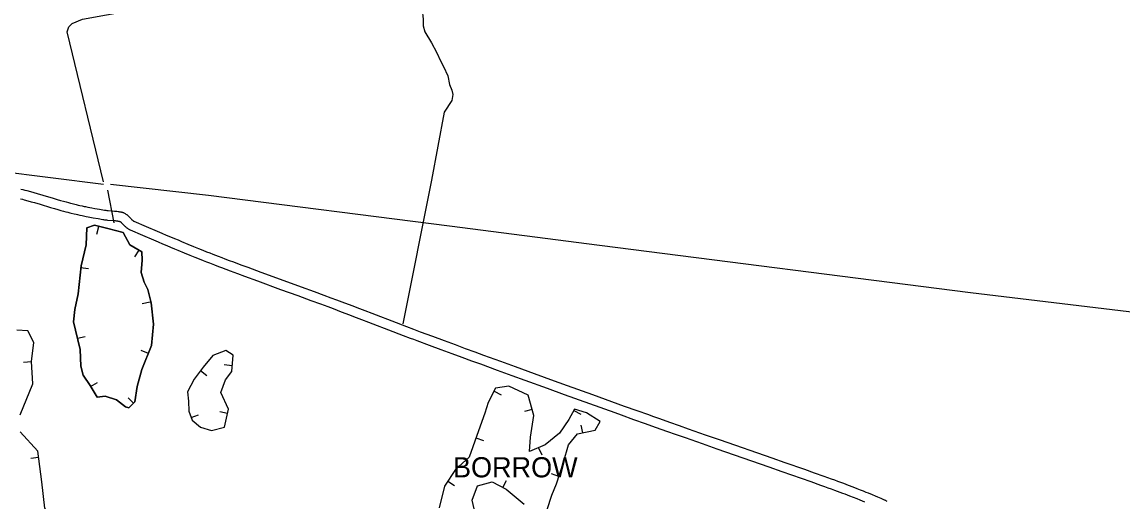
# Model space of a CAD drawing. Extents: x 3177185 to 3215018, y 812988 to 838321.
# Drawn here: x 3191874 to 3195360, y 832285 to 833803 of the extents above; entities that cross this region are included whole.
import ezdxf

# ---------------------------------------------------------------- set-up
doc = ezdxf.new("R2010")
doc.units = 0
for name, color, linetype in [('V-BORW-IDEN', 7, 'Continuous'), ('V-BORW-LINE', 7, 'Continuous'), ('V-ROAD-CNTR', 7, 'Continuous'), ('V-TOPO-SHOR', 7, 'Continuous')]:
    doc.layers.add(name, color=color, linetype=linetype)

msp = doc.modelspace()

# ---------------------------------------------------------------- linework, layer by layer
at = {"layer": 'V-BORW-LINE'}
for p, q in [((3192111, 833130.8), (3192117.2, 833155)), ((3192111, 833130.8), (3192117.2, 833155)), ((3192231.8, 833058.5), (3192244.6, 833079.9)), ((3192231.8, 833058.5), (3192244.6, 833079.9)), ((3192084.3, 833021), (3192059.4, 833023.7)), ((3192084.3, 833021), (3192059.4, 833023.7)), ((3192255.1, 832910.3), (3192279.4, 832916.2)), ((3192255.1, 832910.3), (3192279.4, 832916.2)), ((3192074.1, 832805.2), (3192049.9, 832799.3)), ((3192074.1, 832805.2), (3192049.9, 832799.3)), ((3192250.3, 832762.3), (3192273.5, 832753)), ((3192250.3, 832762.3), (3192273.5, 832753)), ((3191903.9, 832725.6), (3191878.9, 832723.9)), ((3192439, 832697.9), (3192459.1, 832683)), ((3192439, 832697.9), (3192459.1, 832683)), ((3192539.6, 832713.7), (3192514.7, 832716)), ((3192539.6, 832713.7), (3192514.7, 832716)), ((3192111.8, 832659), (3192090.2, 832646.4)), ((3192111.8, 832659), (3192090.2, 832646.4)), ((3193368.7, 832632.7), (3193390.9, 832621.1)), ((3193368.7, 832632.7), (3193390.9, 832621.1)), ((3192210.2, 832611.7), (3192227.8, 832594)), ((3192210.2, 832611.7), (3192227.8, 832594)), ((3192409.6, 832549.3), (3192433, 832558.2)), ((3192409.6, 832549.3), (3192433, 832558.2)), ((3192524.7, 832561.9), (3192500.3, 832567.4)), ((3192524.7, 832561.9), (3192500.3, 832567.4)), ((3193489.2, 832575.2), (3193465.1, 832568.3)), ((3193489.2, 832575.2), (3193465.1, 832568.3)), ((3193621.4, 832571.9), (3193643.3, 832559.9)), ((3193621.4, 832571.9), (3193643.3, 832559.9)), ((3193649.6, 832500.9), (3193644.4, 832525.4)), ((3193649.6, 832500.9), (3193644.4, 832525.4)), ((3193311.2, 832484.6), (3193334.8, 832476.3)), ((3193311.2, 832484.6), (3193334.8, 832476.3)), ((3193509.9, 832453.5), (3193519.8, 832430.6)), ((3193509.9, 832453.5), (3193519.8, 832430.6)), ((3191926.7, 832422.7), (3191901.9, 832419.3)), ((3193574, 832362.7), (3193550.3, 832370.5)), ((3193574, 832362.7), (3193550.3, 832370.5)), ((3193222.5, 832347.8), (3193243.3, 832333.9)), ((3193222.5, 832347.8), (3193243.3, 832333.9)), ((3193396.9, 832327.3), (3193408.5, 832349.5)), ((3193396.9, 832327.3), (3193408.5, 832349.5))]:
    msp.add_line(p, q, dxfattribs=at)
for points in [[(3192051.5, 832941.9), (3192041.4, 832891.3), (3192037.2, 832852.6), (3192043.6, 832825.9), (3192058.4, 832765), (3192060.6, 832712.5), (3192067.9, 832683.4), (3192090.1, 832651.2), (3192111.7, 832614.1), (3192137.8, 832617.1), (3192173.7, 832605.1), (3192201.3, 832583.4), (3192212.6, 832580.3), (3192231.3, 832598.9), (3192238.8, 832647.9), (3192253.5, 832701.4), (3192283.8, 832777.3), (3192290.4, 832845.5), (3192283.3, 832912.8), (3192273, 832955.3), (3192260.5, 832978.4), (3192251.5, 833008.6), (3192254.8, 833048.6), (3192253, 833074.4), (3192215.6, 833096.9), (3192194.5, 833135.5), (3192146.1, 833148.5), (3192103.6, 833159.5), (3192079.4, 833150.2), (3192077.6, 833097), (3192061, 833030.1), (3192051.5, 832941.9)], [(3192051.5, 832941.9), (3192041.4, 832891.3), (3192037.2, 832852.6), (3192043.6, 832825.9), (3192058.4, 832765), (3192060.6, 832712.5), (3192067.9, 832683.4), (3192090.1, 832651.2), (3192111.7, 832614.1), (3192137.8, 832617.1), (3192173.7, 832605.1), (3192201.3, 832583.4), (3192212.6, 832580.3), (3192231.3, 832598.9), (3192238.8, 832647.9), (3192253.5, 832701.4), (3192283.8, 832777.3), (3192290.4, 832845.5), (3192283.3, 832912.8), (3192273, 832955.3), (3192260.5, 832978.4), (3192251.5, 833008.6), (3192254.8, 833048.6), (3192253, 833074.4), (3192215.6, 833096.9), (3192194.5, 833135.5), (3192146.1, 833148.5), (3192103.6, 833159.5), (3192079.4, 833150.2), (3192077.6, 833097), (3192061, 833030.1), (3192051.5, 832941.9)], [(3192051.5, 832941.9), (3192061, 833030.1), (3192077.6, 833097), (3192079.4, 833150.2), (3192103.6, 833159.5), (3192146.1, 833148.5), (3192194.5, 833135.5), (3192215.6, 833096.9), (3192253, 833074.4), (3192254.8, 833048.6), (3192251.5, 833008.6), (3192260.5, 832978.4), (3192273, 832955.3), (3192283.3, 832912.8), (3192290.4, 832845.5), (3192283.8, 832777.3), (3192253.5, 832701.4), (3192238.8, 832647.9), (3192231.3, 832598.9), (3192212.6, 832580.3), (3192201.3, 832583.4), (3192173.7, 832605.1), (3192137.8, 832617.1), (3192111.7, 832614.1), (3192090.1, 832651.2), (3192067.9, 832683.4), (3192060.6, 832712.5), (3192058.4, 832765), (3192043.6, 832825.9), (3192037.2, 832852.6), (3192041.4, 832891.3), (3192051.5, 832941.9)], [(3191867.8, 832557.7), (3191908.8, 832655.8), (3191903.8, 832726.8), (3191911.7, 832787.1), (3191893.1, 832824), (3191857.7, 832826.7)], [(3191867.8, 832557.7), (3191908.8, 832655.8), (3191903.8, 832726.8), (3191911.7, 832787.1), (3191893.1, 832824), (3191857.7, 832826.7)], [(3192398.1, 832631), (3192401.4, 832601.2), (3192401.9, 832569.5), (3192412.9, 832540.7), (3192439.6, 832518.7), (3192473.8, 832508.1), (3192514.9, 832518.4), (3192527.8, 832575.5), (3192503.5, 832629), (3192518.3, 832668.9), (3192538, 832695.4), (3192542.6, 832747.5), (3192519.8, 832761.3), (3192478.6, 832745.4), (3192447.5, 832709.4), (3192419.1, 832671), (3192398.1, 832631)], [(3192398.1, 832631), (3192401.4, 832601.2), (3192401.9, 832569.5), (3192412.9, 832540.7), (3192439.6, 832518.7), (3192473.8, 832508.1), (3192514.9, 832518.4), (3192527.8, 832575.5), (3192503.5, 832629), (3192518.3, 832668.9), (3192538, 832695.4), (3192542.6, 832747.5), (3192519.8, 832761.3), (3192478.6, 832745.4), (3192447.5, 832709.4), (3192419.1, 832671), (3192398.1, 832631)], [(3192398.1, 832631), (3192401.4, 832601.2), (3192401.9, 832569.5), (3192412.9, 832540.7), (3192439.6, 832518.7), (3192473.8, 832508.1), (3192514.9, 832518.4), (3192527.8, 832575.5), (3192503.5, 832629), (3192518.3, 832668.9), (3192538, 832695.4), (3192542.6, 832747.5), (3192519.8, 832761.3), (3192478.6, 832745.4), (3192447.5, 832709.4), (3192419.1, 832671), (3192398.1, 832631)], [(3193536.8, 832258.2), (3193552, 832303.6), (3193566.2, 832338.9), (3193589, 832408), (3193604.5, 832463.1), (3193632.8, 832497.3), (3193688.8, 832509.2), (3193704.5, 832537), (3193660.9, 832564.2), (3193623.3, 832575.4), (3193605.7, 832543.3), (3193576.1, 832500), (3193530.7, 832462.4), (3193481.4, 832441.3), (3193484.5, 832486.9), (3193494.8, 832555.5), (3193476.4, 832619.8), (3193415, 832648.5), (3193373.6, 832642), (3193349.9, 832596.6), (3193339.4, 832563)], [(3193536.8, 832258.2), (3193552, 832303.6), (3193566.2, 832338.9), (3193589, 832408), (3193604.5, 832463.1), (3193632.8, 832497.3), (3193688.8, 832509.2), (3193704.5, 832537), (3193660.9, 832564.2), (3193623.3, 832575.4), (3193605.7, 832543.3), (3193576.1, 832500), (3193530.7, 832462.4), (3193481.4, 832441.3), (3193484.5, 832486.9), (3193494.8, 832555.5), (3193476.4, 832619.8), (3193415, 832648.5), (3193373.6, 832642), (3193349.9, 832596.6), (3193339.4, 832563)], [(3193536.8, 832258.2), (3193552, 832303.6), (3193566.2, 832338.9), (3193589, 832408), (3193604.5, 832463.1), (3193632.8, 832497.3), (3193688.8, 832509.2), (3193704.5, 832537), (3193660.9, 832564.2), (3193623.3, 832575.4), (3193605.7, 832543.3), (3193576.1, 832500), (3193530.7, 832462.4), (3193481.4, 832441.3), (3193484.5, 832486.9), (3193494.8, 832555.5), (3193476.4, 832619.8), (3193415, 832648.5), (3193373.6, 832642), (3193349.9, 832596.6), (3193339.4, 832563)], [(3193339.4, 832563), (3193319.4, 832507.6), (3193290, 832424.2), (3193246.9, 832384.3), (3193211.4, 832331.3), (3193195.2, 832262.9)], [(3193339.4, 832563), (3193319.4, 832507.6), (3193290, 832424.2), (3193246.9, 832384.3), (3193211.4, 832331.3), (3193195.2, 832262.9)], [(3193339.4, 832563), (3193319.4, 832507.6), (3193290, 832424.2), (3193246.9, 832384.3), (3193211.4, 832331.3), (3193195.2, 832262.9)], [(3191810.7, 831911), (3191876.3, 831875.8), (3191898.5, 831875.4), (3191917.8, 831916.5), (3191935.8, 831952.8), (3191974.8, 831978.4), (3191988.9, 832025), (3191959.1, 832091.2), (3191964.7, 832123.3), (3191999.1, 832156.6), (3191977.3, 832206.3), (3191945.9, 832262.4), (3191937.2, 832345.7), (3191923.9, 832442.6), (3191867.9, 832504.1)], [(3191810.7, 831911), (3191876.3, 831875.8), (3191898.5, 831875.4), (3191917.8, 831916.5), (3191935.8, 831952.8), (3191974.8, 831978.4), (3191988.9, 832025), (3191959.1, 832091.2), (3191964.7, 832123.3), (3191999.1, 832156.6), (3191977.3, 832206.3), (3191945.9, 832262.4), (3191937.2, 832345.7), (3191923.9, 832442.6), (3191867.9, 832504.1)], [(3193318.9, 832205.4), (3193299.2, 832287.7), (3193316.3, 832332.6), (3193363, 832345.2), (3193407.5, 832321.8), (3193464, 832274.6)], [(3193318.9, 832205.4), (3193299.2, 832287.7), (3193316.3, 832332.6), (3193363, 832345.2), (3193407.5, 832321.8), (3193464, 832274.6)], [(3193318.9, 832205.4), (3193299.2, 832287.7), (3193316.3, 832332.6), (3193363, 832345.2), (3193407.5, 832321.8), (3193464, 832274.6)]]:
    msp.add_lwpolyline(points, dxfattribs=at)
at = {"layer": 'V-ROAD-CNTR'}
for points in [[(3191869.5, 833242.9), (3191875.5, 833241.2), (3191881.4, 833239.7), (3191892.8, 833236.5), (3191903.4, 833233.5), (3191913.3, 833230.6), (3191932.1, 833225.1), (3191964.8, 833215.4), (3191977.2, 833211.8), (3191988, 833208.7), (3191997.5, 833206), (3192005.9, 833203.7), (3192013.2, 833201.8), (3192019.6, 833200.1), (3192025.2, 833198.6), (3192030.2, 833197.3), (3192038.8, 833195.2), (3192045.3, 833193.6), (3192050.2, 833192.5), (3192057.6, 833190.8), (3192065, 833189.2), (3192069.1, 833188.3), (3192076.8, 833186.8), (3192083.4, 833185.5)], [(3191870.8, 833273.5), (3191877.2, 833271.9), (3191883.4, 833270.2), (3191889.3, 833268.6), (3191900.9, 833265.4), (3191911.6, 833262.3), (3191921.7, 833259.4), (3191940.5, 833253.9), (3191973.3, 833244.2), (3191985.5, 833240.6), (3191996.2, 833237.6), (3192005.6, 833234.9), (3192013.8, 833232.7), (3192020.9, 833230.7), (3192027.2, 833229.1), (3192032.7, 833227.7), (3192037.5, 833226.4), (3192045.9, 833224.3), (3192052.3, 833222.8), (3192057, 833221.7), (3192064.1, 833220.1), (3192071.3, 833218.5), (3192075.2, 833217.7), (3192082.6, 833216.2), (3192089.2, 833214.9)], [(3192089.1, 833214.9), (3192094.8, 833213.9), (3192104.9, 833212), (3192120, 833209.4), (3192135.2, 833206.7), (3192136.7, 833206.5), (3192139.6, 833206.1), (3192142.3, 833205.7), (3192145, 833205.4), (3192147.4, 833205.2), (3192167.4, 833203.7), (3192170.1, 833203.4), (3192172.5, 833203.2), (3192174.6, 833203), (3192178.2, 833202.5), (3192181, 833202.1), (3192183.1, 833201.7), (3192186.2, 833201.1), (3192187.9, 833200.8), (3192189.5, 833200.4), (3192190.7, 833200.1), (3192191.8, 833199.8), (3192193, 833199.4), (3192195, 833198.7), (3192196.9, 833197.9), (3192198.7, 833197), (3192200.3, 833196.1), (3192201.9, 833195.1), (3192203.3, 833194.2), (3192204.6, 833193.3), (3192205.8, 833192.3), (3192206.9, 833191.4), (3192208, 833190.5), (3192209.8, 833188.9), (3192211.5, 833187.3), (3192213, 833185.7), (3192215.5, 833183.1), (3192219.6, 833178.8), (3192221, 833177.4), (3192222.1, 833176.3), (3192223.1, 833175.4), (3192223.9, 833174.6), (3192224.6, 833174.1), (3192225.2, 833173.6), (3192225.6, 833173.3), (3192226, 833173), (3192226.7, 833172.5), (3192227.2, 833172.2), (3192227.5, 833172.1), (3192228, 833171.8), (3192228.7, 833171.5), (3192267.6, 833154.8), (3192301.8, 833140.1), (3192316.8, 833133.7), (3192330.9, 833127.7), (3192344.1, 833122.1), (3192356.5, 833116.9), (3192368.1, 833112.1), (3192379, 833107.5), (3192399.4, 833099), (3192417.3, 833091.7), (3192433, 833085.3), (3192446.7, 833079.8), (3192458.7, 833075), (3192469.3, 833070.8), (3192478.5, 833067.2), (3192494.7, 833060.9), (3192506.8, 833056.2), (3192515.9, 833052.7), (3192529.6, 833047.5), (3192543.3, 833042.4), (3192566.9, 833033.7), (3192589, 833025.6), (3192630.5, 833010.3), (3192703.2, 832983.8), (3192757.8, 832963.8), (3192798.7, 832948.8), (3192829.3, 832937.5), (3192852.3, 832929), (3192869.5, 832922.5), (3192895.4, 832912.9), (3192921.2, 832903.1), (3192934.6, 832898), (3192959.7, 832888.5), (3192981.7, 832880), (3193058.4, 832850.4), (3193077.6, 832843)], [(3192083.5, 833185.5), (3192089.4, 833184.4), (3192099.6, 833182.5), (3192114.9, 833179.8), (3192130.2, 833177.2), (3192132, 833176.9), (3192135.5, 833176.3), (3192138.8, 833175.9), (3192141.9, 833175.6), (3192144.8, 833175.3), (3192164.9, 833173.8), (3192167.2, 833173.6), (3192169.3, 833173.4), (3192171, 833173.2), (3192174.1, 833172.8), (3192176.3, 833172.4), (3192177.9, 833172.2), (3192180.4, 833171.7), (3192181.5, 833171.5), (3192182.7, 833171.2), (3192182.9, 833171.1), (3192183.2, 833171.1), (3192183.3, 833171), (3192183.8, 833170.9), (3192184.3, 833170.7), (3192184.7, 833170.4), (3192185.2, 833170.2), (3192185.7, 833169.9), (3192186.2, 833169.5), (3192186.7, 833169.1), (3192187.3, 833168.7), (3192187.8, 833168.3), (3192188.3, 833167.9), (3192189.5, 833166.9), (3192190.5, 833165.8), (3192191.6, 833164.8), (3192193.8, 833162.5), (3192198, 833158), (3192199.7, 833156.2), (3192201.4, 833154.6), (3192202.9, 833153.2), (3192204.3, 833151.9), (3192205.6, 833150.8), (3192206.8, 833149.9), (3192207.8, 833149.1), (3192208.9, 833148.3), (3192210.6, 833147.2), (3192212, 833146.3), (3192213.2, 833145.7), (3192214.8, 833144.8), (3192216.5, 833144.1), (3192255.8, 833127.2), (3192290.1, 833112.5), (3192305.1, 833106.1), (3192319.2, 833100.1), (3192332.4, 833094.5), (3192344.8, 833089.3), (3192356.5, 833084.4), (3192367.4, 833079.8), (3192388, 833071.3), (3192406, 833063.9), (3192421.7, 833057.5), (3192435.5, 833051.9), (3192447.7, 833047.1), (3192458.3, 833042.9), (3192467.6, 833039.2), (3192483.8, 833032.9), (3192496.1, 833028.2), (3192505.3, 833024.7), (3192519.1, 833019.4), (3192532.9, 833014.3), (3192556.5, 833005.6), (3192578.7, 832997.4), (3192620.2, 832982.2), (3192692.9, 832955.6), (3192747.4, 832935.6), (3192788.3, 832920.6), (3192818.9, 832909.3), (3192841.9, 832900.8), (3192859.1, 832894.4), (3192884.8, 832884.8), (3192910.6, 832875.1), (3192923.9, 832870), (3192949, 832860.4), (3192970.9, 832852), (3193047.7, 832822.4), (3193066.9, 832815)], [(3193077.6, 832843.1), (3193092, 832837.6), (3193113.6, 832829.4), (3193124.4, 832825.3), (3193135.2, 832821.3), (3193174.2, 832806.7), (3193210.8, 832793.1), (3193245.1, 832780.5), (3193277.3, 832768.6), (3193307.4, 832757.5), (3193335.7, 832747.1), (3193388.8, 832727.7), (3193435.3, 832710.8), (3193475.9, 832696), (3193547.1, 832670.2), (3193600.5, 832650.9), (3193680.7, 832621.9), (3193760.8, 832593), (3193781.1, 832585.7), (3193820.5, 832571.6), (3193857.4, 832558.4), (3193870.7, 832553.7)], [(3193066.9, 832815), (3193081.3, 832809.5), (3193103, 832801.3), (3193113.8, 832797.2), (3193124.7, 832793.1), (3193163.7, 832778.6), (3193200.4, 832765), (3193234.7, 832752.3), (3193266.9, 832740.4), (3193297.1, 832729.3), (3193325.4, 832719), (3193378.5, 832699.5), (3193425, 832682.6), (3193465.7, 832667.8), (3193536.9, 832642), (3193590.3, 832622.6), (3193670.5, 832593.7), (3193750.6, 832564.8), (3193771, 832557.4), (3193810.4, 832543.3), (3193847.4, 832530.1), (3193855.5, 832527.2)], [(3193870.7, 832553.7), (3193892.1, 832546.1), (3193924.6, 832534.6), (3193955, 832523.8), (3193983.6, 832513.8), (3194037.2, 832495), (3194084.1, 832478.6), (3194248.5, 832421.2), (3194289.5, 832406.9), (3194351.1, 832385.3), (3194381.9, 832374.4), (3194412.7, 832363.6), (3194424.8, 832359.3), (3194436.1, 832355.2), (3194446.7, 832351.4), (3194456.6, 832347.7), (3194465.9, 832344.3), (3194474.6, 832341), (3194482.7, 832337.9), (3194490.3, 832335), (3194504.6, 832329.5), (3194517.1, 832324.6), (3194528, 832320.3), (3194537.5, 832316.5), (3194545.8, 832313.2), (3194553.1, 832310.2), (3194565.8, 832305), (3194575.3, 832301), (3194582.4, 832298), (3194593.1, 832293.4), (3194603.9, 832288.8), (3194605.3, 832288.2)], [(3193855.5, 832527.2), (3193882.1, 832517.8), (3193914.6, 832506.3), (3193945.1, 832495.5), (3193973.7, 832485.5), (3194027.3, 832466.7), (3194074.3, 832450.3), (3194238.6, 832392.9), (3194279.6, 832378.5), (3194341.2, 832357), (3194372, 832346.1), (3194402.7, 832335.3), (3194414.7, 832331), (3194425.9, 832327), (3194436.4, 832323.2), (3194446.2, 832319.6), (3194455.4, 832316.2), (3194464, 832312.9), (3194472.1, 832309.9), (3194479.6, 832307), (3194493.7, 832301.6), (3194506.1, 832296.7), (3194516.9, 832292.5), (3194526.3, 832288.7), (3194534.5, 832285.4), (3194541.7, 832282.4)], [(3194605.3, 832288.2), (3194605.7, 832288), (3194607.4, 832287), (3194609.1, 832286.1), (3194610.6, 832285.1), (3194612, 832284.1)]]:
    msp.add_lwpolyline(points, dxfattribs=at)
at = {"layer": 'V-TOPO-SHOR'}
for p, q in [((3191209.2, 833406.7), (3192132.3, 833288.6)), ((3192165.7, 833166.4), (3192145.8, 833269.9))]:
    msp.add_line(p, q, dxfattribs=at)
for points in [[(3192132.3, 833296.7), (3192016.9, 833771.7), (3192022.3, 833787.8), (3192033, 833798.5), (3192065.3, 833811.9), (3193012.5, 833983.7), (3193117.2, 834010.5), (3193138.7, 834018.6), (3193138.7, 834026.6), (3193136, 834037.4), (3193144, 834058.8), (3193154.8, 834083), (3193278.2, 834346), (3193506.3, 834885.4), (3193530.5, 834949.8), (3193597.6, 835108.1), (3193857.9, 835073.2), (3194405.3, 835000.8), (3194550.2, 834982), (3194700.5, 834963.2)], [(3193138.7, 834018.6), (3193160.1, 833967.6), (3193160.1, 833951.5), (3193152.1, 833922), (3193144, 833897.8), (3193141.4, 833868.3), (3193141.4, 833841.5), (3193144, 833811.9), (3193144, 833790.5), (3193149.4, 833771.7), (3193170.9, 833736.8), (3193187, 833707.3), (3193200.4, 833677.8), (3193208.4, 833661.7), (3193221.9, 833632.1), (3193227.2, 833605.3), (3193235.3, 833586.5), (3193238, 833573.1), (3193235.3, 833554.3), (3193211.1, 833516.7), (3193170.9, 833302.1), (3193079.6, 832845.9)], [(3192153.8, 833288.6), (3192465.1, 833253.8), (3193227.2, 833157.1), (3193702.2, 833095.4), (3194877.6, 832945.1), (3195457.3, 832875.4)]]:
    msp.add_lwpolyline(points, dxfattribs=at)

# ---------------------------------------------------------------- texts
at = {"layer": 'V-BORW-IDEN'}
msp.add_text('BORROW', height=64, dxfattribs=at).set_placement((3193238.7, 832359.6))

doc.saveas('drawing.dxf')
